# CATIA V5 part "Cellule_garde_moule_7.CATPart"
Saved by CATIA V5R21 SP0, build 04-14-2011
Part number: Moule_cellule_garde
Bounding box of the stored display mesh (mm): x -18 to 18, y -85 to 85, z -17 to 0
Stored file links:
  C:\Users\zerma\Pictures\Stage Stomate\Moule_4 pas utiliser\Cellule_garde_moule_7.CATPart
  Product1.CATProduct
  C:\Users\zerma\Pictures\Moule\Moule_v1.CATPart
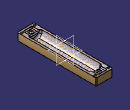
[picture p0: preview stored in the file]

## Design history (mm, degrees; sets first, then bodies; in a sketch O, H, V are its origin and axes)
Body1 (main body)
  Sketch1 on yz-plane, origin (0, 0, 0), H (0, 1, 0), V (0, 0, 1)
    line L1 (-95, -12.5) -> (95, -12.5)
    point P1 (-95, -12.5)
    line L2 (-100, -17.5) -> (100, -17.5)
    point P3 (-100, -17.5)
    line L3 (-95, -12.5) -> (-95, 0)
    point P5 (-95, 0)
    line L4 (-100, -17.5) -> (-100, 0)
    point P6 (-100, 0)
    line L5 (-95, 0) -> (-100, 0)
    point P7 (100, 0)
    point P8 (100, -17.5)
    line L6 (100, -17.5) -> (100, 0)
    point P9 (95, 0)
    line L7 (95, 0) -> (100, 0)
    point P10 (95, -12.5)
    line L8 (95, -12.5) -> (95, 0)
    distance L1 H = 12.5
    distance L1 L2 = 5
    distance L4 L3 = 5
    length L1 = 190
    length L2 = 200
    distance V L3 = 95
    horizontal: L1 H, L2 H, L5 H
    vertical: L3 V, L4 V
    symmetry: P6 P7 V, P3 P8 V, L4 L6 V, P5 P9 V, L5 L7 V, P1 P10 V, L3 L8 V
    coincidence: L5 H
  Shaft1: profile Sketch1, axis Sketch1.H, angle 360
  Sketch2 on face of Shaft1 from Sketch1.L4, origin (0, -100, 0), H (1, 0, 0), V (0, 0, 1)
    line L1 (-10, 2.5) -> (10, 2.5)
    line L2 (10, 2.5) -> (10, -2.5)
    line L3 (10, -2.5) -> (-10, -2.5)
    line L4 (-10, -2.5) -> (-10, 2.5)
    length L2 = 5
    length L1 = 20
    horizontal: L1 H, L3 H
    vertical: L2 V, L4 V
    symmetry: L3 L1 H, L4 L2 V
  Pad1: profile Sketch2, direction (0, -1, 0), length 15
  Sketch3 on face of Pad1 from Sketch2.L1, origin (0, 0, 2.5), H (1, 0, 0), V (0, 1, 0)
    circle A1 centre (0, -107.5) radius 2.5
    point P1 (0, -107.5)
    reference intersected line E1 (17.3205, -100) -> (-17.3205, -100) from face of Shaft1 from Sketch1.L4
    radius A1 = 2.5
    distance P1 E1 = 7.5
    coincidence: P1 V
  Pocket1: profile Sketch3, direction (0, 0, -1), length 5, mirrored extent
  Fillet1: radius 2, on edge [face of Pad1 from Sketch2.L4 | end face of Pad1]; edge [face of Pad1 from Sketch2.L1 | end face of Pad1]; edge [face of Pad1 from Sketch2.L3 | end face of Pad1]; edge [face of Pad1 from Sketch2.L2 | end face of Pad1]; edge [face of Pad1 from Sketch2.L2 | face of Pad1 from Sketch2.L3]; edge [face of Shaft1 from Sketch1.L4 | face of Pad1 from Sketch2.L3]; edge [face of Pad1 from Sketch2.L3 | face of Pad1 from Sketch2.L4]; edge [face of Pocket1 from Sketch3.A1 | face of Pad1 from Sketch2.L3]; edge [face of Pad1 from Sketch2.L4 | face of Pad1 from Sketch2.L1]; edge [face of Pad1 from Sketch2.L1 | face of Pad1 from Sketch2.L2]; edge [face of Shaft1 from Sketch1.L4 | face of Pad1 from Sketch2.L1]; edge [face of Shaft1 from Sketch1.L4 | face of Pad1 from Sketch2.L4]; edge [face of Shaft1 from Sketch1.L4 | face of Pad1 from Sketch2.L2]; face of Pad1 from Sketch2.L1
  Mirror1: of Pad1, Pocket1, Fillet1, about zx-plane
  Fillet2: radius 4, on edge [face of Shaft1 from Sketch1.L2 | face of Shaft1 from Sketch1.L6]; edge [face of Shaft1 from Sketch1.L4 | face of Shaft1 from Sketch1.L2]
Body2
  Sketch4 on xy-plane, origin (0, 0, 0), H (1, 0, 0), V (0, 1, 0)
    line L1 (18, 85) -> (18, -85)
    line L2 (18, -85) -> (-18, -85)
    line L3 (-18, -85) -> (-18, 85)
    line L4 (-18, 85) -> (18, 85)
    length L1 = 170
    length L4 = 36
    vertical: L1 V, L3 V
    horizontal: L2 H, L4 H
    equidistance: L1 L3 O, L2 L4 O
  Pad2: profile Sketch4, direction (0, 0, -1), length 17
  Sketch5 on end face of Pad2, origin (0, 0, -17), H (1, 0, 0), V (0, -1, 0)
    circle A1 centre (14, 79) radius 2.25
    point P1 (14, 79)
    circle A2 centre (14, -79) radius 2.25
    circle A3 centre (-14, 79) radius 2.25
    circle A4 centre (-14, -79) radius 2.25
    reference projected line E1 (18, 85) -> (18, -85) from edge [end face of Pad2 | face of Pad2 from Sketch4.L1]
    reference projected line E2 (-30, 85) -> (30, 85) from edge [end face of Pad2 | face of Pad2 from Sketch4.L2]
    radius A1 = 2.25
    distance P1 E1 = 4
    distance P1 E2 = 6
    symmetry: A1 A2 H, A1 A3 V, A3 A4 H
  Pocket2: profile Sketch5, direction (0, 0, 1), length 50, mirrored extent
  Chamfer1: length 2, angle 45, on edge [face of Pad2 from Sketch4.L4 | face of Pad2 from Sketch4.L3]; edge [end face of Pad2 | face of Pad2 from Sketch4.L4]; edge [end face of Pad2 | face of Pad2 from Sketch4.L3]; edge [face of Pad2 from Sketch4.L1 | face of Pad2 from Sketch4.L4]; edge [end face of Pad2 | face of Pad2 from Sketch4.L1]; edge [end face of Pad2 | face of Pad2 from Sketch4.L2]; edge [face of Pad2 from Sketch4.L2 | face of Pad2 from Sketch4.L1]; edge [face of Pad2 from Sketch4.L3 | face of Pad2 from Sketch4.L2]
  Body3
    Sketch6 on yz-plane, origin (0, 0, 0), H (0, 1, 0), V (0, 0, 1)
      line L1 (-61, -8) -> (61, -8)
      point P2 (61, -8)
      line L2 (-66, -13.5) -> (66, -13.5)
      point P4 (66, -13.5)
      line L3 (-61, -8) -> (-61, 0)
      point P5 (-61, 0)
      line L4 (-66, -13.5) -> (-66, 0)
      line L5 (-61, 0) -> (-66, 0)
      point P8 (66, -13.5)
      line L6 (66, -13.5) -> (66, 0)
      point P9 (61, 0)
      line L7 (61, 0) -> (66, 0)
      point P10 (61, -8)
      line L8 (61, -8) -> (61, 0)
      distance L1 H = 8
      distance L1 L2 = 5.5
      distance L4 L3 = 5
      distance V L3 = 61
      length L7 = 5
      horizontal: L1 H, L2 H, L5 H
      vertical: L3 V, L4 V
      symmetry: L4 L6 V, P5 P9 V, L3 L8 V
      coincidence: L5 H, P4 P8, P2 P10
    Shaft2: profile Sketch6, axis Sketch6.H, angle 360
    Sketch7 on face of Shaft2 from Sketch6.L4, origin (0, -66, 0), H (1, 0, 0), V (0, 0, 1)
      line L1 (-10, 2.5) -> (10, 2.5)
      line L2 (10, 2.5) -> (10, -2.5)
      line L3 (10, -2.5) -> (-10, -2.5)
      line L4 (-10, -2.5) -> (-10, 2.5)
      length L2 = 5
      length L1 = 20
      horizontal: L1 H, L3 H
      vertical: L2 V, L4 V
      symmetry: L3 L1 H, L4 L2 V
    Pad3: profile Sketch7, direction (0, -1, 0), length 15
    Sketch8 on face of Pad3 from Sketch7.L1, origin (0, 0, 2.5), H (1, 0, 0), V (0, 1, 0)
      circle A1 centre (0, -73.5) radius 2.5
      point P1 (0, -73.5)
      reference intersected line E1 (13.2665, -66) -> (-13.2665, -66) from face of Shaft2 from Sketch6.L4
      radius A1 = 2.5
      distance P1 E1 = 7.5
      coincidence: P1 V
    Pocket3: profile Sketch8, direction (0, 0, -1), length 5, mirrored extent
    Fillet3: radius 2, on edge [face of Pad3 from Sketch7.L4 | end face of Pad3]; edge [face of Pad3 from Sketch7.L1 | end face of Pad3]; edge [face of Pad3 from Sketch7.L3 | end face of Pad3]; edge [face of Pad3 from Sketch7.L2 | end face of Pad3]; edge [face of Pad3 from Sketch7.L2 | face of Pad3 from Sketch7.L3]; edge [face of Shaft2 from Sketch6.L4 | face of Pad3 from Sketch7.L3]; edge [face of Pad3 from Sketch7.L3 | face of Pad3 from Sketch7.L4]; edge [face of Pocket3 from Sketch8.A1 | face of Pad3 from Sketch7.L3]; edge [face of Pad3 from Sketch7.L4 | face of Pad3 from Sketch7.L1]; edge [face of Pad3 from Sketch7.L1 | face of Pad3 from Sketch7.L2]; edge [face of Shaft2 from Sketch6.L4 | face of Pad3 from Sketch7.L1]; edge [face of Shaft2 from Sketch6.L4 | face of Pad3 from Sketch7.L4]; edge [face of Shaft2 from Sketch6.L4 | face of Pad3 from Sketch7.L2]; face of Pad3 from Sketch7.L1
    Mirror2: of Pad3, Pocket3, Fillet3, about zx-plane
    Fillet4: radius 4, on edge [face of Shaft2 from Sketch6.L2 | face of Shaft2 from Sketch6.L6]; edge [face of Shaft2 from Sketch6.L4 | face of Shaft2 from Sketch6.L2]
  Remove1: tool Body3
  Sketch9 on face of Shaft2 from Sketch6.L3, origin (0, -61, 0), H (1, 0, 0), V (0, 0, 1)
    circle A1 centre (0, 0) radius 8
    reference projected circle E1 centre (0, 0) radius 8 from edge [face of Shaft2 from Sketch6.L3 | face of Shaft2 from Sketch6.L1]
    coincidence: A1 E1
  Pocket4: profile Sketch9, direction (0, 1, 0), up to face of Shaft2 from Sketch6.L8
  Sketch10 on start face of Pad2, origin (0, 0, 0), H (1, 0, 0), V (0, 1, 0)
    circle A1 centre (0, 73.5) radius 2.5
    reference projected circle E1 centre (0, 73.5) radius 2.5 from edge [face of Mirror2 | start face of Pad2]
    circle A2 centre (0, -73.5) radius 2.5
    reference projected circle E2 centre (0, -73.5) radius 2.5 from edge [face of Pocket3 from Sketch8.A1 | start face of Pad2]
    coincidence: A1 E1, A2 E2
  Pocket5: profile Sketch10, direction (0, 0, -1), up to end face of Pad2
  CLDGeom1 "Maillage.1"
  CLDGeom2 "Maillage.2"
